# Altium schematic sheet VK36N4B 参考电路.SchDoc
size A4
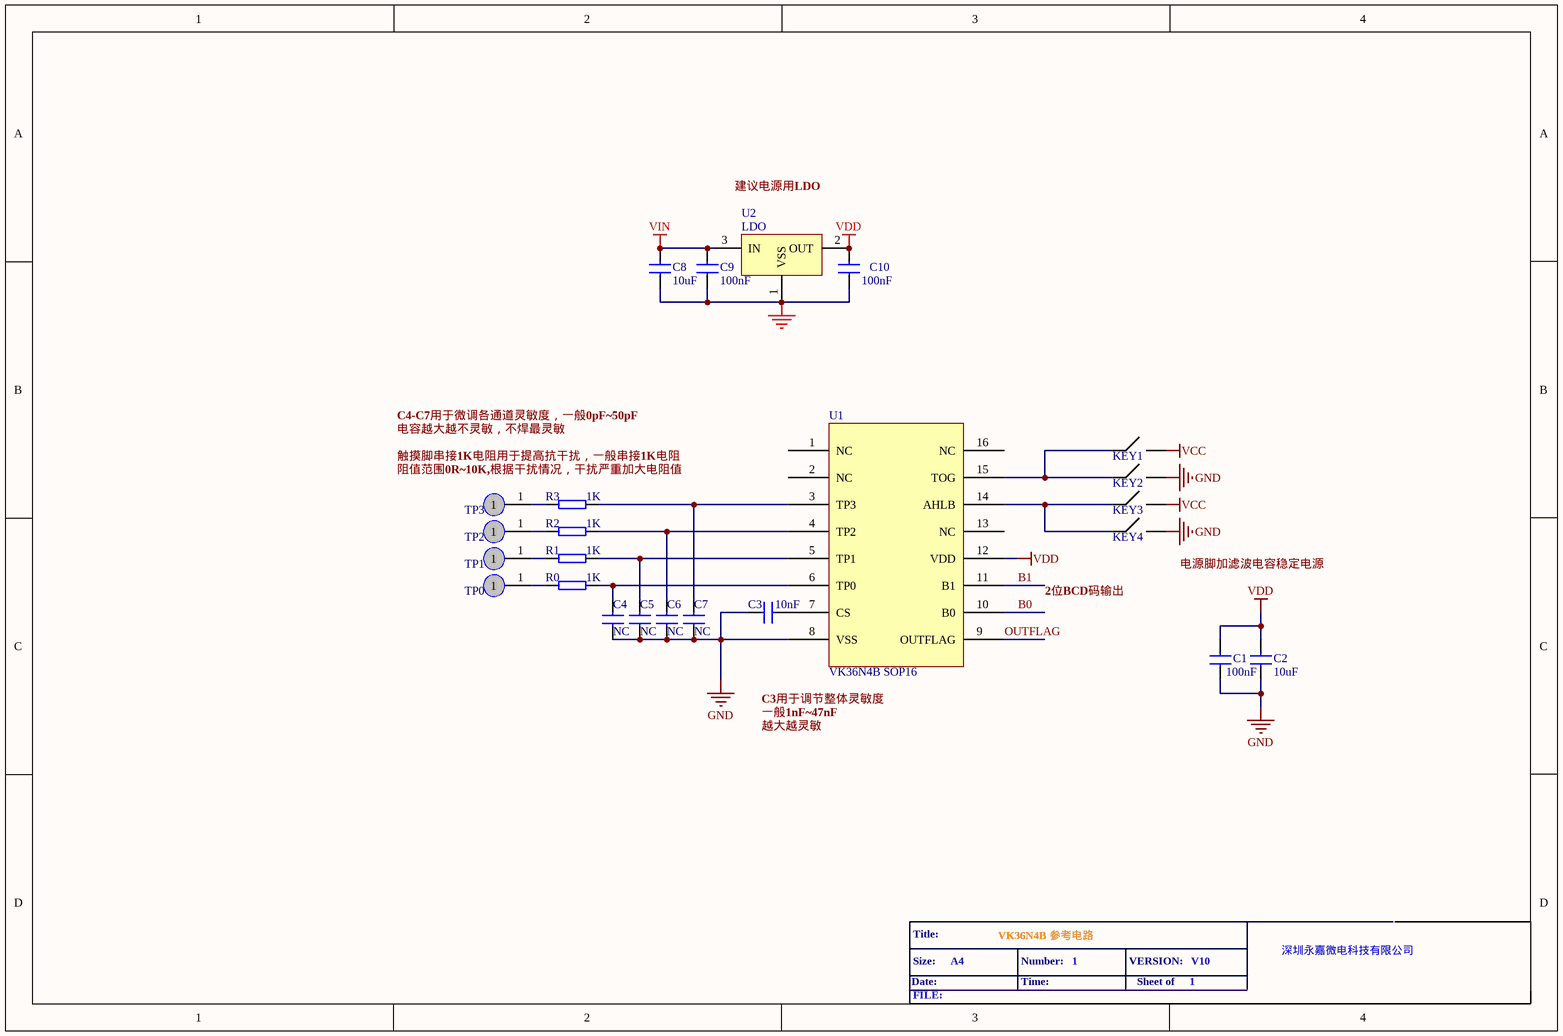
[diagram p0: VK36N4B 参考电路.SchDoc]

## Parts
C1  100nF  [0603-C]
C2  10uF  [0603-C]
C3  value 10nF  [0603-C]  (hidden comment: 10uF)
C4  value NC  [0603-C]  (hidden comment: 10uF)
C5  value NC  [0603-C]  (hidden comment: 10uF)
C6  value NC  [0603-C]  (hidden comment: 10uF)
C7  value NC  [0603-C]  (hidden comment: 10uF)
C8  10uF  [0805-C]
C9  100nF  [0805-C]
C10  100nF  [0805-C]
KEY1  单刀单掷开关  (value not drawn)
KEY2  单刀单掷开关  (value not drawn)
KEY3  单刀单掷开关  (value not drawn)
KEY4  单刀单掷开关  (value not drawn)
R0  1K  [0603-R]
R1  1K  [0603-R]
R2  1K  [0603-R]
R3  1K  [0603-R]
TP0  TPAD  [TP-PAD0]  (value not drawn)
TP1  TPAD  [TP-PAD0]  (value not drawn)
TP2  TPAD  [TP-PAD0]  (value not drawn)
TP3  TPAD  [TP-PAD0]  (value not drawn)
U1  VK36N4B SOP16
U2  LDO  [SOT-23]

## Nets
GND: C1.2 C2.2 C3.2 C4.1 C5.1 C6.1 C7.1 C8.2 C9.2 C10.2 U1.8(VSS) U2.1(VSS)
VDD: C1.1 C2.1 C10.1 U1.12(VDD) U2.2(OUT)
VIN: C8.1 C9.1 U2.3(IN)
B0: U1.10(B0)
B1: U1.11(B1)
OUTFLAG: U1.9(OUTFLAG)
NetC3_1: C3.1 U1.7(CS)
NetC4_2: C4.2 R0.2 U1.6(TP0)
NetC5_2: C5.2 R1.1 U1.5(TP1)
NetC6_2: C6.2 R2.1 U1.4(TP2)
NetC7_2: C7.2 R3.1 U1.3(TP3)
NetR0_1: R0.1 TP0.1
NetR1_2: R1.2 TP1.1
NetR2_2: R2.2 TP2.1
NetR3_2: R3.2 TP3.1

Not connected (* = marked no-connect by the designer): U1 1(NC) 2(NC) 13(NC) 14(AHLB) 15(TOG) 16(NC)

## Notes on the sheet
- 建议电源用LDO
- C4-C7用于微调各通道灵敏度，一般0pF~50pF
- 电容越大越不灵敏，不焊最灵敏
- 触摸脚串接1K电阻用于提高抗干扰，一般串接1K电阻
- 阻值范围0R
  0K,根据干扰情况，干扰严重加大电阻值
- (near KEY4) 电源脚加滤波电容稳定电源
- 2位BCD码输出
- C3用于调节整体灵敏度
- 一般1nF~47nF
- 越大越灵敏
- Date:
- Title:
- Size:
- A4
- VK36N4B 参考电路
- Number:
- Time:
- 1
- VERSION:
- Sheet of
- V10
- 深圳永嘉微电科技有限公司
- FILE:
- Labels drawn without touching a wire or pin: GND, VCC

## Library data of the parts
C1-C10 = CAP: Capacitor
R0-R3 = RES: Resistor
TP0-TP3 = TPAD: TESTING
U2 = V6206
